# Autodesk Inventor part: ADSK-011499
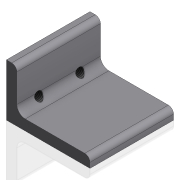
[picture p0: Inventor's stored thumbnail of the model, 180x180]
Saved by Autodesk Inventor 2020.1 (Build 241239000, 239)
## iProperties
Created: 2000-02
Part Number: ADSK-011499
Material: RA HRS
Document SubType Name: Modeling
Designer: sspink
Density: 7.83 g/cm^3
Appearance: Métal - Acier
Mass: 190.921 g
Surface Area: 92.444 cm^2
Volume: 24.3832 cm^3
Control State: 0
Checked Out: False
Master: False
Shininess: 0.0
Length Units: 11269
Angle Units: 11279
Time Units: 11290
Mass Units: 11283
Length Display Precision: 3
Angle Display Precision: 2
Compacted: True
Cutlength: 2
Material Desc: ANGLE,HRS,0.250 X 2.00 X 1.25
Material_number: A085014
Dimensions: 50,8x31,7x50,8 mm
Mass: 0,191 kg
Density: 0.0
Volumn: 0.0
Area: 0.0
PropertySet Name: Model Information
Author: sspink
Revision Number: -
Title: ADSK-011499
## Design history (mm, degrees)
node "Element2:1"
node "Hole1" dims "d11" = 4.917, "d12" = 9.525, "d13" = 6.35, "d14" = 60 deg, "d15" = 17.1, "d16" = 118 deg, "d18" = 12
  sketch "Sketch3"
    geometry: L1 (0, 31.75)-(50.8, 31.75) reference; L2 (37.9, 9.75)-(12.9, 9.75); 2 further points
    constraints: 2 end point, 2 midpoint, 1 horizontal, 1 horizontal alignment, 1 vertical alignment
    dimensions: "d8" = 22 distance from line of L2.start L1; "d17" = 25 distance of L2.start L2.end
node "Solide1"
node "Corps solides"
node "Corps surfaciques"
sketch "Sketch1"
  geometry: L1 (50.8, 0)-(50.8, 31.75) reference; L2 (0, 31.75)-(50.8, 31.75) reference; L3 (0, 31.75)-(0, 0) reference; L4 (0, 0)-(50.8, 0) reference
sketch "Sketch2"
  geometry: L1 (32.408, 38.758)-(83.208, 38.758); L2 (32.408, 70.508)-(32.408, 38.758); L3 (38.758, 67.333)-(38.758, 50.188); L4 (43.838, 45.108)-(80.033, 45.108); L5 (32.408, 70.508)-(35.583, 70.508); L6 (83.208, 41.933)-(83.208, 38.758); A1 r 3.175 centre (35.583, 67.333) between (38.758, 67.333) and (35.583, 70.508); A2 r 3.175 centre (80.033, 41.933) between (83.208, 41.933) and (80.033, 45.108); A3 r 5.08 centre (43.838, 50.188) between (38.758, 50.188) and (43.838, 45.108); 1 further point
  constraints: 12 end point, 6 point on circle, 6 tangent, 3 centre point, 1 coincident, 1 equal radius, 1 horizontal, 1 perpendicular, 1 other
  dimensions: "d0" = 6.35 distance between parallel lines of L2 L3 (derived); "d3" = 3.175 radius of A1 (derived); "d4" = 5.08 radius of A3 (derived); "d1" = 31.75 distance between parallel lines of L1 L5 (derived); "d2" = 50.8 distance between parallel lines of L6 L2 (derived)
